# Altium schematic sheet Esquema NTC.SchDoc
size A4
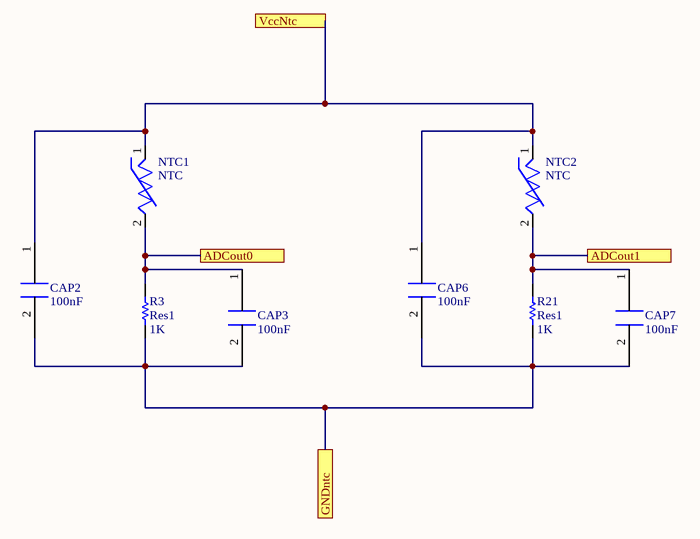
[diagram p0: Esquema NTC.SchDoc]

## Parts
CAP2  100nF  [Capacitor Eletro]
CAP3  100nF  [Capacitor Eletro]
CAP6  100nF  [Capacitor Eletro]
CAP7  100nF  [Capacitor Eletro]
NTC1  NTC  [NTC]
NTC2  NTC  [NTC]
R3  Res1  value 1K  [AXIAL-0.3]
R21  Res1  value 1K  [AXIAL-0.3]

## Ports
ADCout0, ADCout1, GNDntc, VccNtc

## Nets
ADCout0: CAP3.1 NTC1.2 R3.2 ; port ADCout0
ADCout1: CAP7.1 NTC2.2 R21.2 ; port ADCout1
GNDntc: CAP2.2 CAP3.2 CAP6.2 CAP7.2 R3.1 R21.1 ; port GNDntc
VccNtc: CAP2.1 CAP6.1 NTC1.1 NTC2.1 ; port VccNtc

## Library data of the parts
CAP2 CAP3 CAP6 CAP7 = 33pF: Condensador
R3 R21 = Res1: Resistor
